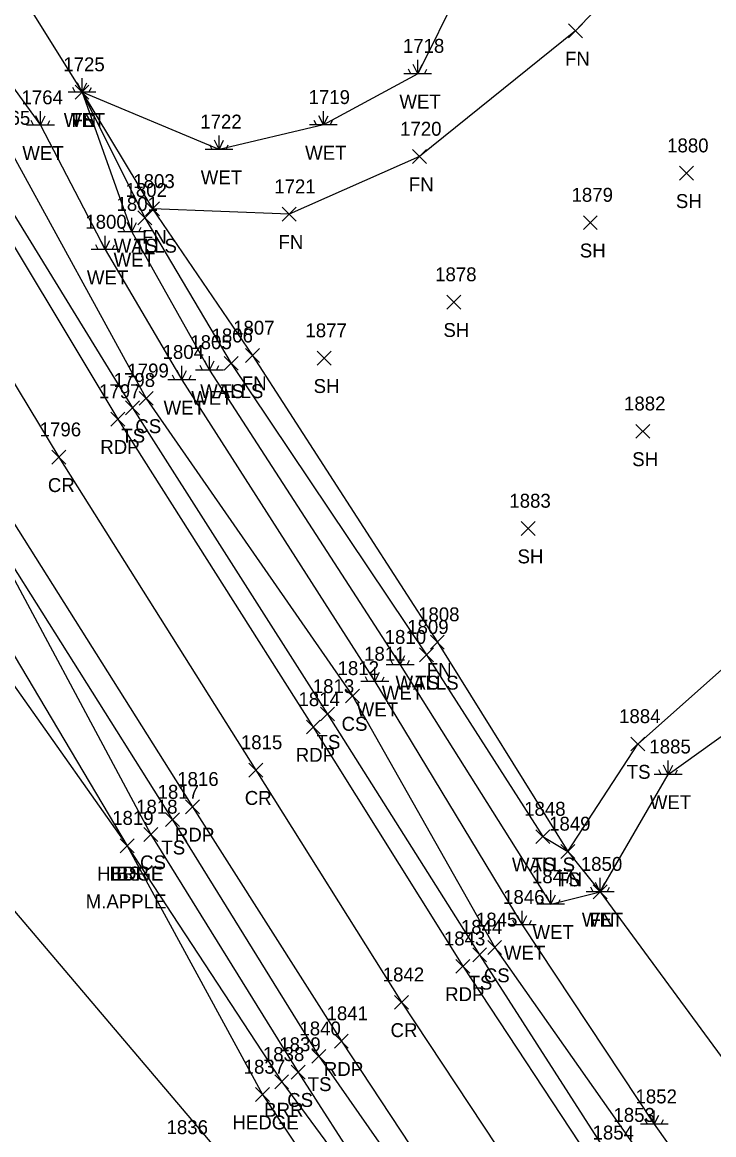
# Model space of a CAD drawing. Extents: x 1501299 to 1502485, y 381423 to 383765.
# Drawn here: x 1501417.5 to 1501516.8, y 383498.2 to 383658 of the extents above; entities that cross this region are included whole.
import ezdxf

# ---------------------------------------------------------------- set-up
doc = ezdxf.new("R2010")
doc.units = 0
for name, color, linetype in [('L_A', 7, 'Continuous'), ('L_C', 7, 'Continuous'), ('L_I', 7, 'Continuous'), ('L_TIC', 7, 'Continuous'), ('LABL', 7, 'Continuous'), ('LAHR', 7, 'Continuous'), ('LELB', 7, 'Continuous'), ('LFNC', 7, 'Continuous'), ('LWET', 7, 'Continuous'), ('LWS', 7, 'Continuous'), ('P_A', 7, 'Continuous'), ('P_I', 7, 'Continuous'), ('P_TIC', 7, 'Continuous'), ('PET', 7, 'Continuous'), ('PRC', 7, 'Continuous')]:
    doc.layers.add(name, color=color, linetype=linetype)

msp = doc.modelspace()

# ---------------------------------------------------------------- linework, layer by layer
at = {"layer": 'L_TIC'}
for points in [[(1501495.93, 383655.8), (1501497.93, 383657.8)], [(1501497.93, 383655.8), (1501495.93, 383657.8)], [(1501425.09, 383646.98), (1501427.09, 383648.98)], [(1501427.09, 383646.98), (1501425.09, 383648.98)], [(1501425.09, 383646.98), (1501427.09, 383648.98)], [(1501427.09, 383646.98), (1501425.09, 383648.98)], [(1501473.52, 383637.72), (1501475.52, 383639.72)], [(1501475.52, 383637.72), (1501473.52, 383639.72)], [(1501511.85, 383635.33), (1501513.85, 383637.33)], [(1501513.85, 383635.33), (1501511.85, 383637.33)], [(1501434.1, 383628.92), (1501436.1, 383630.92)], [(1501436.1, 383628.92), (1501434.1, 383630.92)], [(1501434.1, 383628.92), (1501436.1, 383630.92)], [(1501436.1, 383628.92), (1501434.1, 383630.92)], [(1501435.22, 383630.2), (1501437.22, 383632.2)], [(1501437.22, 383630.2), (1501435.22, 383632.2)], [(1501435.22, 383630.2), (1501437.22, 383632.2)], [(1501437.22, 383630.2), (1501435.22, 383632.2)], [(1501454.81, 383629.44), (1501456.81, 383631.44)], [(1501456.81, 383629.44), (1501454.81, 383631.44)], [(1501498.05, 383628.23), (1501500.05, 383630.23)], [(1501500.05, 383628.23), (1501498.05, 383630.23)], [(1501478.47, 383616.81), (1501480.47, 383618.81)], [(1501480.47, 383616.81), (1501478.47, 383618.81)], [(1501446.51, 383608.02), (1501448.51, 383610.02)], [(1501448.51, 383608.02), (1501446.51, 383610.02)], [(1501446.51, 383608.02), (1501448.51, 383610.02)], [(1501448.51, 383608.02), (1501446.51, 383610.02)], [(1501449.55, 383609.14), (1501451.55, 383611.14)], [(1501451.55, 383609.14), (1501449.55, 383611.14)], [(1501459.84, 383608.76), (1501461.84, 383610.76)], [(1501461.84, 383608.76), (1501459.84, 383610.76)], [(1501432.32, 383601.63), (1501434.32, 383603.63)], [(1501434.32, 383601.63), (1501432.32, 383603.63)], [(1501434.3, 383602.99), (1501436.3, 383604.99)], [(1501436.3, 383602.99), (1501434.3, 383604.99)], [(1501505.57, 383598.25), (1501507.57, 383600.25)], [(1501507.57, 383598.25), (1501505.57, 383600.25)], [(1501489.11, 383584.28), (1501491.11, 383586.28)], [(1501491.11, 383584.28), (1501489.11, 383586.28)], [(1501476.09, 383567.96), (1501478.09, 383569.96)], [(1501478.09, 383567.96), (1501476.09, 383569.96)], [(1501474.53, 383566.14), (1501476.53, 383568.14)], [(1501476.53, 383566.14), (1501474.53, 383568.14)], [(1501474.53, 383566.14), (1501476.53, 383568.14)], [(1501476.53, 383566.14), (1501474.53, 383568.14)], [(1501463.9, 383560.23), (1501465.9, 383562.23)], [(1501465.9, 383560.23), (1501463.9, 383562.23)], [(1501460.34, 383557.64), (1501462.34, 383559.64)], [(1501462.34, 383557.64), (1501460.34, 383559.64)], [(1501504.86, 383553.33), (1501506.86, 383555.33)], [(1501506.86, 383553.33), (1501504.86, 383555.33)], [(1501438.07, 383542.46), (1501440.07, 383544.46)], [(1501440.07, 383542.46), (1501438.07, 383544.46)], [(1501434.97, 383540.32), (1501436.97, 383542.32)], [(1501436.97, 383540.32), (1501434.97, 383542.32)], [(1501491.24, 383540.02), (1501493.24, 383542.02)], [(1501493.24, 383540.02), (1501491.24, 383542.02)], [(1501491.24, 383540.02), (1501493.24, 383542.02)], [(1501493.24, 383540.02), (1501491.24, 383542.02)], [(1501431.56, 383538.71), (1501433.56, 383540.71)], [(1501433.56, 383538.71), (1501431.56, 383540.71)], [(1501431.56, 383538.71), (1501433.56, 383540.71)], [(1501433.56, 383538.71), (1501431.56, 383540.71)], [(1501431.56, 383538.71), (1501433.56, 383540.71)], [(1501433.56, 383538.71), (1501431.56, 383540.71)], [(1501494.83, 383537.88), (1501496.83, 383539.88)], [(1501496.83, 383537.88), (1501494.83, 383539.88)], [(1501494.83, 383537.88), (1501496.83, 383539.88)], [(1501496.83, 383537.88), (1501494.83, 383539.88)], [(1501499.46, 383532.1), (1501501.46, 383534.1)], [(1501501.46, 383532.1), (1501499.46, 383534.1)], [(1501484.32, 383524.1), (1501486.32, 383526.1)], [(1501486.32, 383524.1), (1501484.32, 383526.1)], [(1501482.16, 383523.05), (1501484.16, 383525.05)], [(1501484.16, 383523.05), (1501482.16, 383525.05)], [(1501459.07, 383508.46), (1501461.07, 383510.46)], [(1501461.07, 383508.46), (1501459.07, 383510.46)], [(1501456.1, 383506.19), (1501458.1, 383508.19)], [(1501458.1, 383506.19), (1501456.1, 383508.19)], [(1501453.75, 383504.78), (1501455.75, 383506.78)], [(1501455.75, 383504.78), (1501453.75, 383506.78)], [(1501450.98, 383502.96), (1501452.98, 383504.96)], [(1501452.98, 383502.96), (1501450.98, 383504.96)]]:
    msp.add_lwpolyline(points, dxfattribs=at)
at = {"layer": 'LABL'}
for points in [[(1501349.77, 383634.07), (1501358.61, 383636.91), (1501365.75, 383641.19), (1501375.86, 383617.1), (1501401.99, 383582.97), (1501432.56, 383539.71), (1501454.75, 383505.78), (1501467.78, 383488.13), (1501464.27, 383485.42), (1501459.99, 383478.86)], [(1501365.08, 383604.09), (1501372.27, 383598.02), (1501384.53, 383567.86), (1501459.99, 383478.86)]]:
    msp.add_lwpolyline(points, dxfattribs=at)
at = {"layer": 'LAHR'}
msp.add_lwpolyline([(1501432.56, 383539.71), (1501451.98, 383503.96), (1501464.27, 383485.42)], dxfattribs=at)
at = {"layer": 'LELB'}
for points in [[(1501358.62, 383732.98), (1501381.14, 383696.09), (1501398.69, 383667.71), (1501415.46, 383640.29), (1501435.3, 383603.99), (1501464.9, 383561.23), (1501485.32, 383525.1), (1501505.06, 383497.04), (1501522.93, 383468.15), (1501546.42, 383435.55), (1501564.6, 383407.15), (1501589.27, 383369.8), (1501600.38, 383363.76)], [(1501355.51, 383731.14), (1501378.37, 383693.86), (1501395.55, 383665.66), (1501411.45, 383638.21), (1501433.32, 383602.63), (1501461.34, 383558.64), (1501483.16, 383524.05), (1501502.07, 383494.51), (1501520.43, 383466.23), (1501542.02, 383433.96), (1501561.69, 383405.4), (1501588.28, 383366.16), (1501592.45, 383361.85)], [(1501332.79, 383719.08), (1501356.21, 383681.5), (1501373.29, 383652.69), (1501388.57, 383624.23), (1501410.59, 383588.65), (1501439.07, 383543.46), (1501460.07, 383509.46), (1501480.49, 383480.19), (1501499.63, 383452.74), (1501519.17, 383422.52), (1501533.38, 383399.88)], [(1501324.47, 383715.68), (1501351.26, 383678.54), (1501366.23, 383650.78), (1501368.72, 383645.59), (1501384.78, 383621.73), (1501405.54, 383585.19), (1501432.56, 383539.71)], [(1501426.09, 383647.98), (1501435.1, 383629.92)], [(1501447.51, 383609.02), (1501475.53, 383567.14)], [(1501410.59, 383588.65), (1501435.97, 383541.32), (1501457.1, 383507.19), (1501476.16, 383477.48), (1501479.31, 383471.05), (1501488.94, 383457.91)], [(1501492.24, 383541.02), (1501495.83, 383538.88), (1501505.86, 383554.33), (1501523.46, 383569.96), (1501537.91, 383571.58), (1501549.82, 383585.69)]]:
    msp.add_lwpolyline(points, dxfattribs=at)
at = {"layer": 'LFNC'}
for points in [[(1501374.37, 383742.56), (1501382.94, 383727.21), (1501403.34, 383685.19), (1501409.51, 383674.58), (1501426.09, 383647.98), (1501436.22, 383631.2), (1501450.55, 383610.14), (1501477.09, 383568.96), (1501495.83, 383538.88), (1501500.46, 383533.1), (1501519.53, 383507.11), (1501541.76, 383477.61), (1501544.05, 383474.54), (1501551.42, 383461.96)], [(1501511.83, 383672.59), (1501496.93, 383656.8), (1501474.52, 383638.72), (1501455.81, 383630.44), (1501436.22, 383631.2)]]:
    msp.add_lwpolyline(points, dxfattribs=at)
at = {"layer": 'LWET'}
for p, q in [((1501474.27, 383650.63), (1501473.6, 383651.96)), ((1501474.27, 383650.63), (1501474.27, 383652.63)), ((1501474.27, 383650.63), (1501474.93, 383651.96)), ((1501426.09, 383647.98), (1501426.09, 383649.98)), ((1501476.27, 383650.63), (1501472.27, 383650.63)), ((1501473.27, 383650.63), (1501472.93, 383651.3)), ((1501475.27, 383650.63), (1501475.6, 383651.3)), ((1501425.09, 383647.98), (1501424.76, 383648.65)), ((1501426.09, 383647.98), (1501425.43, 383649.31)), ((1501426.09, 383647.98), (1501426.76, 383649.31)), ((1501427.09, 383647.98), (1501427.43, 383648.65)), ((1501428.09, 383647.98), (1501424.09, 383647.98)), ((1501420.14, 383643.24), (1501420.14, 383645.24)), ((1501460.73, 383643.27), (1501460.73, 383645.27)), ((1501419.14, 383643.24), (1501418.81, 383643.91)), ((1501420.14, 383643.24), (1501419.48, 383644.58)), ((1501420.14, 383643.24), (1501420.81, 383644.58)), ((1501421.14, 383643.24), (1501421.48, 383643.91)), ((1501459.73, 383643.27), (1501459.4, 383643.93)), ((1501460.73, 383643.27), (1501460.06, 383644.6)), ((1501460.73, 383643.27), (1501461.4, 383644.6)), ((1501461.73, 383643.27), (1501462.06, 383643.93)), ((1501422.14, 383643.24), (1501418.14, 383643.24)), ((1501462.73, 383643.27), (1501458.73, 383643.27)), ((1501444.76, 383639.75), (1501444.42, 383640.41)), ((1501445.76, 383639.75), (1501445.09, 383641.08)), ((1501445.76, 383639.75), (1501445.76, 383641.75)), ((1501445.76, 383639.75), (1501446.42, 383641.08)), ((1501446.76, 383639.75), (1501447.09, 383640.41)), ((1501447.76, 383639.75), (1501443.76, 383639.75)), ((1501433.24, 383627.92), (1501432.57, 383629.25)), ((1501433.24, 383627.92), (1501433.24, 383629.92)), ((1501433.24, 383627.92), (1501433.91, 383629.25)), ((1501435.24, 383627.92), (1501431.24, 383627.92)), ((1501432.24, 383627.92), (1501431.91, 383628.59)), ((1501434.24, 383627.92), (1501434.57, 383628.59)), ((1501428.42, 383625.36), (1501428.08, 383626.03)), ((1501429.42, 383625.36), (1501428.75, 383626.69)), ((1501429.42, 383625.36), (1501429.42, 383627.36)), ((1501429.42, 383625.36), (1501430.08, 383626.69)), ((1501430.42, 383625.36), (1501430.75, 383626.03)), ((1501431.42, 383625.36), (1501427.42, 383625.36)), ((1501444.4, 383608.06), (1501444.4, 383610.06)), ((1501440.42, 383606.65), (1501440.42, 383608.65)), ((1501443.4, 383608.06), (1501443.06, 383608.73)), ((1501444.4, 383608.06), (1501443.73, 383609.4)), ((1501444.4, 383608.06), (1501445.06, 383609.4)), ((1501445.4, 383608.06), (1501445.73, 383608.73)), ((1501442.42, 383606.65), (1501438.42, 383606.65)), ((1501439.42, 383606.65), (1501439.09, 383607.32)), ((1501440.42, 383606.65), (1501439.75, 383607.98)), ((1501440.42, 383606.65), (1501441.09, 383607.98)), ((1501441.42, 383606.65), (1501441.75, 383607.32)), ((1501446.4, 383608.06), (1501442.4, 383608.06)), ((1501471.74, 383565.71), (1501471.07, 383567.04)), ((1501471.74, 383565.71), (1501471.74, 383567.71)), ((1501471.74, 383565.71), (1501472.41, 383567.04)), ((1501468.13, 383563.3), (1501468.13, 383565.3)), ((1501473.74, 383565.71), (1501469.74, 383565.71)), ((1501470.74, 383565.71), (1501470.41, 383566.37)), ((1501472.74, 383565.71), (1501473.07, 383566.37)), ((1501467.13, 383563.3), (1501466.79, 383563.97)), ((1501468.13, 383563.3), (1501467.46, 383564.63)), ((1501468.13, 383563.3), (1501468.79, 383564.63)), ((1501469.13, 383563.3), (1501469.46, 383563.97)), ((1501470.13, 383563.3), (1501466.13, 383563.3)), ((1501510.21, 383549.97), (1501509.54, 383551.3)), ((1501510.21, 383549.97), (1501510.21, 383551.97)), ((1501510.21, 383549.97), (1501510.87, 383551.3)), ((1501512.21, 383549.97), (1501508.21, 383549.97)), ((1501509.21, 383549.97), (1501508.87, 383550.63)), ((1501511.21, 383549.97), (1501511.54, 383550.63)), ((1501500.46, 383533.1), (1501500.46, 383535.1)), ((1501493.36, 383531.32), (1501493.36, 383533.32)), ((1501499.46, 383533.1), (1501499.12, 383533.77)), ((1501500.46, 383533.1), (1501499.79, 383534.43)), ((1501500.46, 383533.1), (1501501.12, 383534.43)), ((1501501.46, 383533.1), (1501501.79, 383533.77)), ((1501492.36, 383531.32), (1501492.03, 383531.98)), ((1501493.36, 383531.32), (1501492.7, 383532.65)), ((1501493.36, 383531.32), (1501494.03, 383532.65)), ((1501494.36, 383531.32), (1501494.7, 383531.98)), ((1501502.46, 383533.1), (1501498.46, 383533.1)), ((1501489.26, 383528.35), (1501489.26, 383530.35)), ((1501495.36, 383531.32), (1501491.36, 383531.32)), ((1501491.26, 383528.35), (1501487.26, 383528.35)), ((1501488.26, 383528.35), (1501487.93, 383529.02)), ((1501489.26, 383528.35), (1501488.6, 383529.68)), ((1501489.26, 383528.35), (1501489.93, 383529.68)), ((1501490.26, 383528.35), (1501490.6, 383529.02)), ((1501508.23, 383499.7), (1501508.23, 383501.7)), ((1501510.23, 383499.7), (1501506.23, 383499.7)), ((1501507.23, 383499.7), (1501506.89, 383500.37)), ((1501508.23, 383499.7), (1501507.56, 383501.03)), ((1501508.23, 383499.7), (1501508.89, 383501.03)), ((1501509.23, 383499.7), (1501509.56, 383500.37))]:
    msp.add_line(p, q, dxfattribs=at)
for points in [[(1501368.35, 383738.78), (1501382.94, 383727.21), (1501398.82, 383737.57), (1501418, 383747.31), (1501440.05, 383727.46), (1501471.68, 383717.46), (1501494.57, 383699.38), (1501486.25, 383674.8), (1501474.27, 383650.63), (1501460.73, 383643.27), (1501445.76, 383639.75), (1501426.09, 383647.98), (1501433.24, 383627.92), (1501444.4, 383608.06), (1501471.74, 383565.71), (1501493.36, 383531.32), (1501500.46, 383533.1), (1501510.21, 383549.97), (1501525.64, 383560.99), (1501540.9, 383568.85), (1501552.66, 383578.59)], [(1501361.86, 383735.32), (1501383.52, 383697.56), (1501401.54, 383668.95), (1501420.14, 383643.24), (1501429.42, 383625.36), (1501440.42, 383606.65), (1501468.13, 383563.3), (1501489.26, 383528.35), (1501508.23, 383499.7), (1501528.29, 383471.48), (1501550.47, 383437.33), (1501555.06, 383441.42)]]:
    msp.add_lwpolyline(points, dxfattribs=at)
at = {"layer": 'LWS'}
for points in [[(1501435.1, 383629.92), (1501447.51, 383609.02)], [(1501475.53, 383567.14), (1501492.24, 383541.02)]]:
    msp.add_lwpolyline(points, dxfattribs=at)
at = {"layer": 'P_TIC'}
for points in [[(1501430.22, 383600.01), (1501432.22, 383602.01)], [(1501432.22, 383600.01), (1501430.22, 383602.01)], [(1501421.76, 383594.53), (1501423.76, 383596.53)], [(1501423.76, 383594.53), (1501421.76, 383596.53)], [(1501458.29, 383555.77), (1501460.29, 383557.77)], [(1501460.29, 383555.77), (1501458.29, 383557.77)], [(1501450.02, 383549.58), (1501452.02, 383551.58)], [(1501452.02, 383549.58), (1501450.02, 383551.58)], [(1501440.93, 383544.3), (1501442.93, 383546.3)], [(1501442.93, 383544.3), (1501440.93, 383546.3)], [(1501479.73, 383521.39), (1501481.73, 383523.39)], [(1501481.73, 383521.39), (1501479.73, 383523.39)], [(1501470.94, 383516.22), (1501472.94, 383518.22)], [(1501472.94, 383516.22), (1501470.94, 383518.22)], [(1501462.31, 383510.64), (1501464.31, 383512.64)], [(1501464.31, 383510.64), (1501462.31, 383512.64)]]:
    msp.add_lwpolyline(points, dxfattribs=at)
at = {"layer": 'PET'}
for points in [[(1501352.61, 383730.1), (1501376.04, 383692.66), (1501392.89, 383664.45), (1501409.55, 383637.05), (1501431.22, 383601.01), (1501459.29, 383556.77), (1501480.73, 383522.39), (1501500.04, 383493.11), (1501518.67, 383465.09), (1501539.81, 383433.29), (1501559.66, 383403.85), (1501585.89, 383364.55), (1501607.04, 383333.42), (1501616.49, 383318.82), (1501608.79, 383312.41), (1501601.65, 383306.28)], [(1501334.83, 383720.25), (1501358.01, 383682.47), (1501375.27, 383653.98), (1501391.81, 383626.28), (1501413.67, 383590.16), (1501441.93, 383545.3), (1501463.31, 383511.64), (1501483.05, 383481.71), (1501501.39, 383453.56), (1501521.79, 383422.95), (1501532.7, 383406.6), (1501560.32, 383365.3), (1501580.55, 383335.85), (1501587.21, 383326.16), (1501601.65, 383306.28)]]:
    msp.add_lwpolyline(points, dxfattribs=at)
at = {"layer": 'PRC'}
msp.add_lwpolyline([(1501342.03, 383724.18), (1501367.31, 383687.9), (1501383.59, 383659.52), (1501401.02, 383631.48), (1501422.76, 383595.53), (1501451.02, 383550.58), (1501471.94, 383517.22), (1501491.45, 383487.69), (1501510.59, 383459), (1501530.12, 383428.74), (1501550.99, 383398.39), (1501579.41, 383355.49), (1501608.79, 383312.41)], dxfattribs=at)

# ---------------------------------------------------------------- texts
at = {"layer": 'L_A'}
for s, p in [('FN', (1501495.41, 383651.8)), ('WET', (1501471.64, 383645.63)), ('TS', (1501424.5, 383642.98)), ('WET', (1501423.47, 383642.98)), ('FN', (1501424.57, 383642.98)), ('WET', (1501417.52, 383638.24)), ('WET', (1501458.11, 383638.27)), ('WET', (1501443.13, 383634.75)), ('FN', (1501473, 383633.72)), ('SH', (1501511.33, 383631.33)), ('FN', (1501434.7, 383626.2)), ('FN', (1501434.7, 383626.2)), ('FN', (1501454.29, 383625.44)), ('WALLS', (1501430.64, 383624.92)), ('TS', (1501433.51, 383624.92)), ('SH', (1501497.54, 383624.23)), ('WET', (1501430.62, 383622.92)), ('WET', (1501426.79, 383620.36)), ('SH', (1501477.96, 383612.81)), ('FN', (1501449.03, 383605.14)), ('SH', (1501459.33, 383604.76)), ('WET', (1501441.77, 383603.06)), ('WALLS', (1501443.05, 383604.02)), ('TS', (1501445.91, 383604.02)), ('WET', (1501437.8, 383601.65)), ('CS', (1501433.74, 383598.99)), ('TS', (1501431.73, 383597.63)), ('SH', (1501505.06, 383594.25)), ('SH', (1501488.6, 383580.28)), ('FN', (1501475.57, 383563.96)), ('WALLS', (1501471.08, 383562.14)), ('TS', (1501473.94, 383562.14)), ('WET', (1501469.12, 383560.71)), ('WET', (1501465.51, 383558.3)), ('CS', (1501463.34, 383556.23)), ('TS', (1501459.75, 383553.64)), ('TS', (1501504.27, 383549.33)), ('WET', (1501507.59, 383544.97)), ('TS', (1501437.48, 383538.46)), ('CS', (1501434.42, 383536.32)), ('WALLS', (1501487.79, 383536.02)), ('TS', (1501490.65, 383536.02)), ('HEDGE', (1501428.26, 383534.71)), ('BRR', (1501430.05, 383534.71)), ('BS', (1501431, 383534.71)), ('TS', (1501494.24, 383533.88)), ('FN', (1501494.31, 383533.88)), ('WET', (1501497.83, 383528.1)), ('FN', (1501498.94, 383528.1)), ('WET', (1501490.74, 383526.32)), ('WET', (1501486.64, 383523.35)), ('CS', (1501483.76, 383520.1)), ('TS', (1501481.57, 383519.05)), ('TS', (1501458.48, 383504.46)), ('BRR', (1501452.24, 383500.78)), ('CS', (1501455.54, 383502.19)), ('HEDGE', (1501447.68, 383498.96))]:
    msp.add_text(s, height=2, dxfattribs=at).set_placement(p)
at = {"layer": 'L_C'}
msp.add_text('M.APPLE', height=2, dxfattribs=at).set_placement((1501426.62, 383530.71))
at = {"layer": 'L_I'}
for s, p in [('1718', (1501472.14, 383653.63)), ('1725', (1501423.4, 383650.98)), ('1725', (1501423.4, 383650.98)), ('1725', (1501423.4, 383650.98)), ('1764', (1501417.4, 383646.24)), ('1719', (1501458.6, 383646.27)), ('1765', (1501412.72, 383643.29)), ('1722', (1501443.06, 383642.75)), ('1720', (1501471.74, 383641.72)), ('1880', (1501510.07, 383639.33)), ('1803', (1501433.45, 383634.2)), ('1803', (1501433.45, 383634.2)), ('1721', (1501453.68, 383633.44)), ('1802', (1501432.33, 383632.92)), ('1802', (1501432.33, 383632.92)), ('1879', (1501496.35, 383632.23)), ('1801', (1501431.04, 383630.92)), ('1800', (1501426.56, 383628.36)), ('1878', (1501476.77, 383620.81)), ('1807', (1501447.77, 383613.14)), ('1877', (1501458.15, 383612.76)), ('1805', (1501441.63, 383611.06)), ('1806', (1501444.68, 383612.02)), ('1806', (1501444.68, 383612.02)), ('1804', (1501437.65, 383609.65)), ('1799', (1501432.6, 383606.99)), ('1798', (1501430.63, 383605.63)), ('1882', (1501503.88, 383602.25)), ('1883', (1501487.42, 383588.28)), ('1808', (1501474.32, 383571.96)), ('1809', (1501472.76, 383570.14)), ('1809', (1501472.76, 383570.14)), ('1810', (1501469.53, 383568.71)), ('1811', (1501466.57, 383566.3)), ('1812', (1501462.77, 383564.23)), ('1813', (1501459.21, 383561.64)), ('1884', (1501503.17, 383557.33)), ('1885', (1501507.52, 383552.97)), ('1817', (1501436.94, 383546.46)), ('1818', (1501433.85, 383544.32)), ('1848', (1501489.55, 383544.02)), ('1848', (1501489.55, 383544.02)), ('1819', (1501430.42, 383542.71)), ('1819', (1501430.42, 383542.71)), ('1819', (1501430.42, 383542.71)), ('1849', (1501493.13, 383541.88)), ('1849', (1501493.13, 383541.88)), ('1850', (1501497.68, 383536.1)), ('1850', (1501497.68, 383536.1)), ('1847', (1501490.67, 383534.32)), ('1846', (1501486.52, 383531.35)), ('1845', (1501482.63, 383528.1)), ('1844', (1501480.47, 383527.05)), ('1840', (1501457.29, 383512.46)), ('1838', (1501452.05, 383508.78)), ('1839', (1501454.4, 383510.19)), ('1837', (1501449.29, 383506.96)), ('1852', (1501505.53, 383502.7)), ('1853', (1501502.36, 383500.04)), ('1836', (1501438.22, 383498.28)), ('1854', (1501499.37, 383497.51))]:
    msp.add_text(s, height=2, dxfattribs=at).set_placement(p)
at = {"layer": 'P_A'}
for s, p in [('RDP', (1501428.71, 383596.01)), ('CR', (1501421.19, 383590.53)), ('RDP', (1501456.77, 383551.77)), ('CR', (1501449.45, 383545.58)), ('RDP', (1501439.42, 383540.3)), ('RDP', (1501478.21, 383517.39)), ('CR', (1501470.37, 383512.22)), ('RDP', (1501460.8, 383506.64))]:
    msp.add_text(s, height=2, dxfattribs=at).set_placement(p)
at = {"layer": 'P_I'}
for s, p in [('1797', (1501428.53, 383604.01)), ('1796', (1501420.01, 383598.53)), ('1814', (1501457.16, 383559.77)), ('1815', (1501448.89, 383553.58)), ('1816', (1501439.75, 383548.3)), ('1843', (1501478.03, 383525.39)), ('1842', (1501469.25, 383520.22)), ('1841', (1501461.19, 383514.64))]:
    msp.add_text(s, height=2, dxfattribs=at).set_placement(p)

doc.saveas('drawing.dxf')
